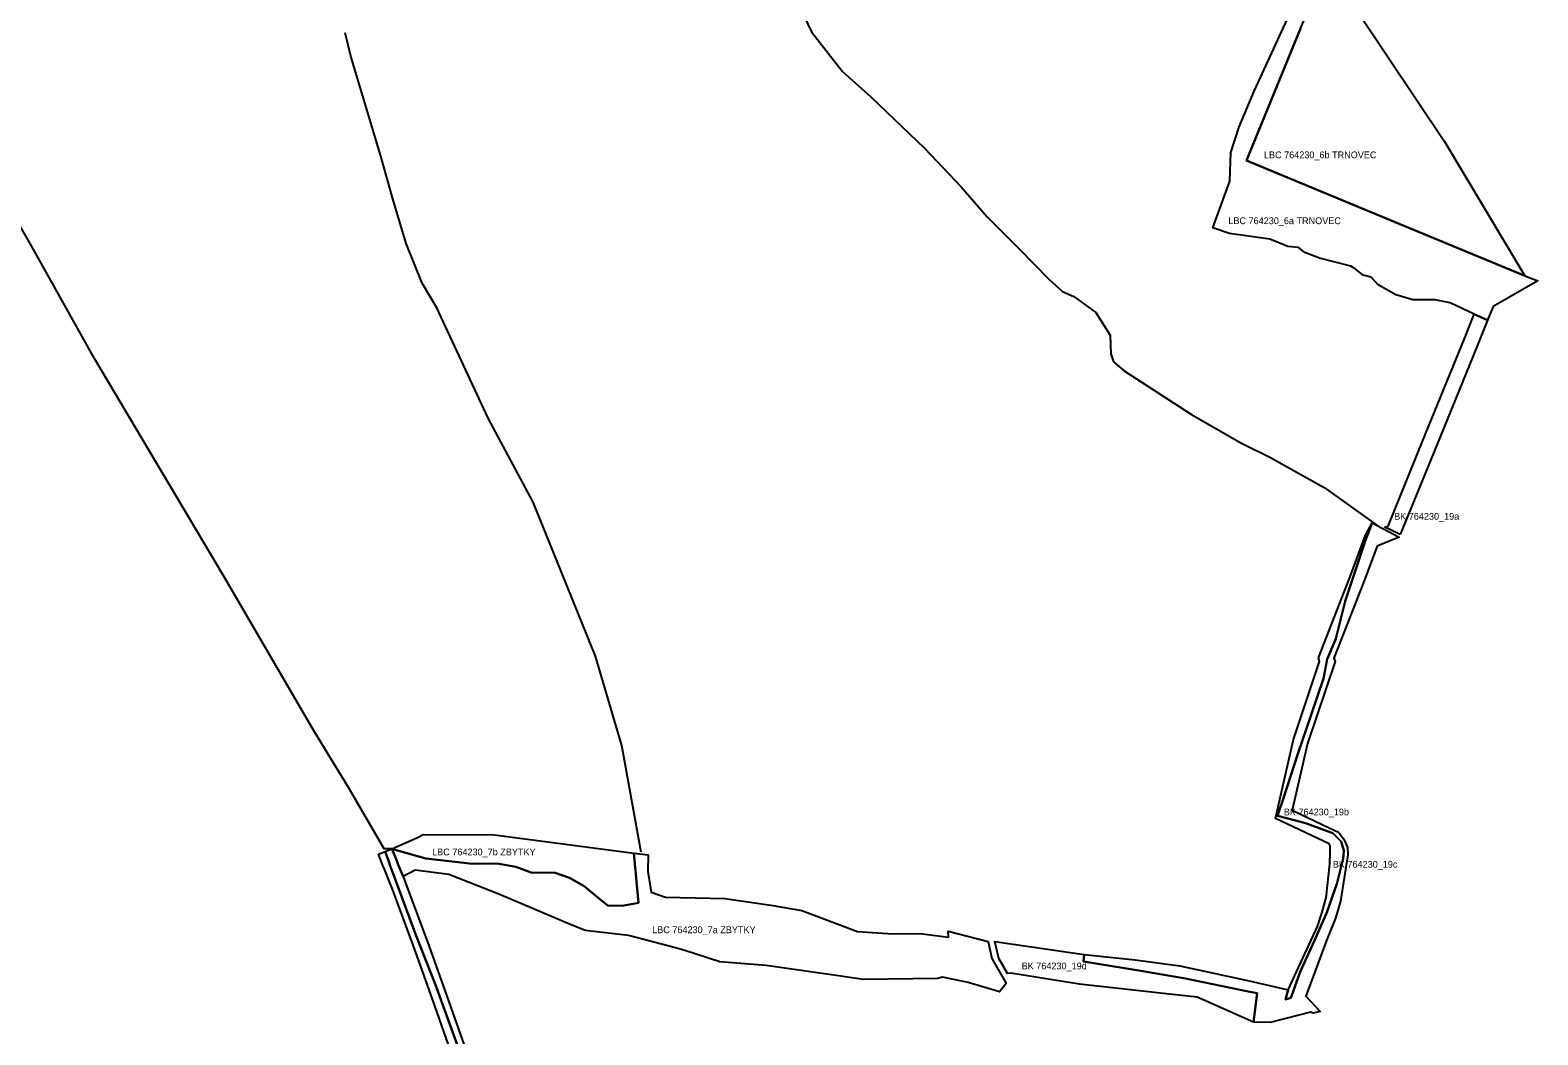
# Model space of a CAD drawing. Extents: x -521616 to -516782, y -1190061 to -1184927.
# Drawn here: x -519440 to -517886, y -1189525 to -1188489 of the extents above; entities that cross this region are included whole.
import ezdxf

# ---------------------------------------------------------------- set-up
doc = ezdxf.new("R2010")
doc.units = 0
for name, color, linetype in [('i_prvek_l_n', 7, 'Continuous'), ('LBC_n', 7, 'Continuous'), ('LBC_s', 7, 'Continuous'), ('LBK_n', 7, 'Continuous'), ('LBK_s', 7, 'Continuous')]:
    doc.layers.add(name, color=color, linetype=linetype)

msp = doc.modelspace()

# ---------------------------------------------------------------- linework, layer by layer
at = {"layer": 'i_prvek_l_n'}
for points in [[(-518657.4, -1188442.6), (-518634.5, -1188491.2), (-518602.7, -1188532.1), (-518573.2, -1188558), (-518518.1, -1188610.9), (-518480.2, -1188650.8), (-518453.4, -1188681.7), (-518420.8, -1188714.4), (-518389.9, -1188745.9), (-518375.7, -1188758.6), (-518364, -1188764), (-518341.3, -1188780.5), (-518326.6, -1188803.7), (-518325.8, -1188822.8), (-518323.3, -1188831.2), (-518312.3, -1188840.3), (-518242.8, -1188885.6), (-518191.8, -1188914.5), (-518161.4, -1188929.7), (-518135.7, -1188944.1), (-518106.1, -1188960.6), (-518051.7, -1188999.4)], [(-518810, -1189336.5), (-518829.9, -1189226.7), (-518857.2, -1189134.6), (-518921.3, -1188975.9), (-518967.8, -1188889.4), (-519020.9, -1188775.6), (-519036, -1188750), (-519052.5, -1188709.3), (-519066.2, -1188663.2), (-519078.5, -1188619.2), (-519109.3, -1188516.1), (-519115.3, -1188492.2)], [(-519067, -1189333.1), (-519075.2, -1189333), (-519110.8, -1189271.6), (-519147.8, -1189210.8), (-519240.1, -1189052.6), (-519373.4, -1188828.5), (-519438.2, -1188712.2), (-519464.9, -1188665.5)]]:
    msp.add_lwpolyline(points, dxfattribs=at)
at = {"layer": 'LBC_n'}
for points in [[(-518107.5, -1188434.2), (-518094.9, -1188429), (-518088.8, -1188444.4), (-518071, -1188471), (-517982, -1188604), (-517899.2, -1188742.7), (-518042.7, -1188683.1), (-518186.2, -1188623.6), (-518130.3, -1188487.5)], [(-519051.8, -1189337.4), (-519067, -1189333.1), (-519041.3, -1189321.8), (-519034.9, -1189318.3), (-518961.3, -1189318.6), (-518817.6, -1189337.4), (-518813, -1189388.8), (-518829.7, -1189391.7), (-518844.5, -1189391.4), (-518852.6, -1189384.9), (-518869, -1189371.4), (-518884.1, -1189363), (-518898.6, -1189357.9), (-518923.6, -1189357.5), (-518939.4, -1189351.8), (-518958.7, -1189348.2), (-518984, -1189348.5), (-519032.1, -1189342.9)]]:
    msp.add_lwpolyline(points, close=True, dxfattribs=at)
at = {"layer": 'LBC_s'}
for points in [[(-518130.3, -1188487.5), (-518186.2, -1188623.6), (-518042.7, -1188683.1), (-517899.2, -1188742.7), (-517885.7, -1188747.6), (-517931.9, -1188774.1), (-517937.7, -1188788.3), (-517951.3, -1188781.9), (-517976.1, -1188770.3), (-517992, -1188767.2), (-518014.7, -1188767.2), (-518032, -1188762.1), (-518050.5, -1188751.9), (-518057.6, -1188744.1), (-518065.8, -1188741.9), (-518074.1, -1188735.3), (-518078.6, -1188732.6), (-518111, -1188724.2), (-518126, -1188718.6), (-518132.5, -1188713.5), (-518143.6, -1188712.3), (-518162.2, -1188704.9), (-518203.6, -1188699), (-518220.9, -1188693), (-518203.4, -1188645), (-518202.2, -1188615.4), (-518193.5, -1188588.9), (-518178.1, -1188552.2), (-518127.5, -1188442.4)], [(-518774.7, -1189435.2), (-518823, -1189422.3), (-518867.8, -1189417.2), (-518886.3, -1189409.8), (-518957, -1189379.7), (-519008.5, -1189359.6), (-519043.2, -1189355), (-519055.4, -1189361.6), (-519060.8, -1189348.5), (-519062.4, -1189344.4), (-519067, -1189333.1), (-519051.8, -1189337.4), (-519032.1, -1189342.9), (-518984, -1189348.5), (-518958.7, -1189348.2), (-518939.4, -1189351.8), (-518923.6, -1189357.5), (-518898.6, -1189357.9), (-518884.1, -1189363), (-518869, -1189371.4), (-518852.6, -1189384.9), (-518844.5, -1189391.4), (-518829.7, -1189391.7), (-518813, -1189388.8), (-518817.6, -1189337.4), (-518803, -1189339.4), (-518803.3, -1189356.6), (-518799.7, -1189377.7), (-518785.1, -1189383)], [(-518785.1, -1189383), (-518723.7, -1189384.4), (-518676.6, -1189391), (-518644.5, -1189396.6), (-518587, -1189418.3), (-518550.7, -1189420.7), (-518522.9, -1189420.5), (-518493.3, -1189424.2), (-518493.5, -1189418), (-518452.5, -1189428.6), (-518448.6, -1189446.2), (-518434, -1189471.8), (-518440.6, -1189480.4), (-518472.9, -1189470.9), (-518499.5, -1189465.5), (-518504.6, -1189466.7), (-518581.3, -1189467.8), (-518606.7, -1189463.8), (-518681.2, -1189453.4), (-518729, -1189449.7), (-518765.1, -1189437.7), (-518774.7, -1189435.2)]]:
    msp.add_lwpolyline(points, dxfattribs=at)
at = {"layer": 'LBK_n'}
for points in [[(-518027.6, -1189009.2), (-518043.4, -1189001.7), (-518040.2, -1189000.4), (-518004.2, -1188912.1), (-517961.8, -1188808.2), (-517951.3, -1188781.9), (-517937.7, -1188788.3), (-517947.9, -1188813.9), (-517990.3, -1188917.8)], [(-518143.2, -1189478.3), (-518113, -1189413), (-518108.4, -1189399.5), (-518103.8, -1189383.6), (-518100.1, -1189348.4), (-518100, -1189336.8), (-518100, -1189329.9), (-518101, -1189327.9), (-518106.6, -1189325.3), (-518156.3, -1189301.9), (-518137.7, -1189220.5), (-518110.7, -1189140), (-518111.9, -1189136.4), (-518079.6, -1189053.3), (-518063.3, -1189009.7), (-518056.6, -1188997), (-518063.7, -1189015.9), (-518084.3, -1189077.7), (-518094.1, -1189116.8), (-518102.9, -1189137.6), (-518106.6, -1189157.5), (-518119.4, -1189194.9), (-518133, -1189235.2), (-518148.2, -1189282), (-518154, -1189299.1), (-518127.6, -1189305.8), (-518123.3, -1189307.4), (-518105.6, -1189313.9), (-518097, -1189317.1), (-518088.5, -1189325.5), (-518085.7, -1189334.8), (-518086.6, -1189343.3), (-518093.1, -1189369.3), (-518103.4, -1189398.7), (-518115.9, -1189427.4), (-518130.9, -1189459.9), (-518138, -1189480.2), (-518140.3, -1189486.6), (-518146, -1189488.2)], [(-518178.7, -1189511.8), (-518237, -1189485.8), (-518259.4, -1189483.4), (-518358.1, -1189472.5), (-518429.1, -1189461.3), (-518432.4, -1189461.6), (-518441.4, -1189446.2), (-518445.5, -1189428.6), (-518353.4, -1189441.9), (-518354.2, -1189449.1), (-518297.2, -1189458.4), (-518248.8, -1189466.6), (-518184.3, -1189480.1), (-518175, -1189481.7)]]:
    msp.add_lwpolyline(points, close=True, dxfattribs=at)
msp.add_lwpolyline([(-519004.7, -1189546.6), (-519025, -1189488.9), (-519042.8, -1189439), (-519066.6, -1189374.5), (-519069.4, -1189367), (-519074.7, -1189354.1), (-519076.3, -1189350.1), (-519080.9, -1189338.7), (-519074.1, -1189335.9), (-519070.4, -1189346), (-519068.7, -1189350.5), (-519063.6, -1189364.5), (-519042, -1189422.7), (-519022.2, -1189473.1), (-518999.6, -1189535.6)], dxfattribs=at)
at = {"layer": 'LBK_s'}
msp.add_lwpolyline([(-518056.6, -1188997), (-518028.7, -1189012), (-518047.1, -1189019.4), (-518051.5, -1189021.2), (-518065.6, -1189058.6), (-518096, -1189136.7), (-518094.8, -1189139.9), (-518123.3, -1189224.6), (-518139, -1189293.4), (-518100.2, -1189311.7), (-518091.3, -1189315.9), (-518085.8, -1189323.2), (-518081.9, -1189331.6), (-518081.7, -1189339.3), (-518089.2, -1189386.9), (-518094.2, -1189404.4), (-518103.7, -1189427.7), (-518125, -1189484.9), (-518110.3, -1189500.7), (-518117.3, -1189502.5), (-518120.1, -1189501.4), (-518132.3, -1189504.6), (-518161.7, -1189512.1), (-518178.7, -1189511.8), (-518175, -1189481.7), (-518184.3, -1189480.1), (-518248.8, -1189466.6), (-518297.2, -1189458.4), (-518354.2, -1189449.1), (-518353.4, -1189441.9), (-518300.8, -1189447.6), (-518254.8, -1189453.8), (-518183.2, -1189469), (-518143.2, -1189478.3), (-518146, -1189488.2), (-518140.3, -1189486.6), (-518138, -1189480.2), (-518130.9, -1189459.9), (-518115.9, -1189427.4), (-518103.4, -1189398.7), (-518093.1, -1189369.3), (-518086.6, -1189343.3), (-518085.7, -1189334.8), (-518088.5, -1189325.5), (-518097, -1189317.1), (-518105.6, -1189313.9), (-518123.3, -1189307.4), (-518127.6, -1189305.8), (-518154, -1189299.1), (-518148.2, -1189282), (-518133, -1189235.2), (-518119.4, -1189194.9), (-518106.6, -1189157.5), (-518102.9, -1189137.6), (-518094.1, -1189116.8), (-518084.3, -1189077.7), (-518063.7, -1189015.9)], close=True, dxfattribs=at)
msp.add_lwpolyline([(-518999.6, -1189535.6), (-519022.2, -1189473.1), (-519042, -1189422.7), (-519063.6, -1189364.5), (-519068.7, -1189350.5), (-519070.4, -1189346), (-519074.1, -1189335.9), (-519067, -1189333.1), (-519062.4, -1189344.4), (-519060.8, -1189348.5), (-519055.4, -1189361.6), (-519052.6, -1189369.3), (-519028.7, -1189433.9), (-519010.8, -1189483.9), (-518990.6, -1189541.4)], dxfattribs=at)

# ---------------------------------------------------------------- texts
at = {"layer": 'LBC_n'}
for s, p in [('LBC 764230_6b TRNOVEC', (-518168.1, -1188621.4)), ('LBC 764230_7b ZBYTKY', (-519025.6, -1189339.8))]:
    msp.add_text(s, height=7, dxfattribs=at).set_placement(p)
at = {"layer": 'LBC_s'}
for s, p in [('LBC 764230_6a TRNOVEC', (-518204.8, -1188689.3)), ('LBC 764230_7a ZBYTKY', (-518798.8, -1189420))]:
    msp.add_text(s, height=7, dxfattribs=at).set_placement(p)
at = {"layer": 'LBK_n'}
for s, p in [('BK 764230_19a', (-518033.9, -1188993.9)), ('BK 764230_19c', (-518097.1, -1189352.5)), ('BK 764230_19d', (-518417.9, -1189457.3))]:
    msp.add_text(s, height=7, dxfattribs=at).set_placement(p)
at = {"layer": 'LBK_s'}
msp.add_text('BK 764230_19b', height=7, dxfattribs=at).set_placement((-518147.6, -1189298.6))

doc.saveas('drawing.dxf')
